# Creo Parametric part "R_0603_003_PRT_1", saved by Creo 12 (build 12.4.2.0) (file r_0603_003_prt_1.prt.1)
Units: Custom; MM, KILOGRAM, SECS

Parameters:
  PTC_WM_ITERATION = "0"
  PTC_WM_VERSION = "-.0"
  PTC_WM_LIFECYCLE_STATE = "In Work"
  PTC_WM_LIFECYCLE = "MO_CADDocument"
  PTC_WM_CREATED_BY = "Maximilian Roepper (Z0017RMS: MO)"
  PTC_WM_CREATED_ON = "18-Sep-26 11:36:42 AM"
  PTC_WM_MODIFIED_BY = "Maximilian Roepper (Z0017RMS: MO)"
  PTC_WM_MODIFIED_ON = "18-Sep-26 11:36:46 AM"
  PDMLINKNUMBER = "PDM000071455049"
  PTC_WM_NAME = "r_0603_003_prt_1.prt"
  PTC_WM_NUMBER = "PDM000071455049"

Other parameters: WEIGHT, WEIGHT_FACTOR, WEIGHT_ADD, _MASS_TEMP, _DIFF_TEMP, MC_ERRORS, SUPPLIER

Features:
  1. coordinate system
  2. datum plane "PRT_YZ"
  3. datum plane "PRT_XY"
  4. datum plane "PRT_XZ"
  5. coordinate system
  6. datum axis
  7. datum axis
  8. datum axis
  9. coordinate system
  10. imported feature
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
Other named items: PRT, SIEMENS_MO, DRW_VIEW_ORG, PRT_X, PRT_Y, PRT_Z, CS0, ROUGH_GROB

Layers: 00_STD_CSYS-KSYS, 01_STD_PLANES-EBENEN, 02_STD_AXES-ACHSEN, 03_STD_CSYS-KSYS, 24_IMPORT_FEAT-IMPORT_KE

Surfaces: 18 plane, 8 cylinder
